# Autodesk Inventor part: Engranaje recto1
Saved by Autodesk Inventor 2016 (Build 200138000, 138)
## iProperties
Created: 2016-06
Part Number: Engranaje recto1
Material: Steel
Document SubType Name: Modeling
Designer: adm
Categories: <?xml version="1.0" encoding="UTF-16"?> <MemberInstance><Categories><FamilyTemplate><FamilyTemplateParameter ValueType="xs:double" Id="1" ObjectReferenceKey="da
Density: 1 g/cm^3
Appearance: Steel
CustomPartVersion: 1
Author: adm
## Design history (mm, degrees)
sketch "Sketch1"
  geometry: C1 r 25 at (0, 0)
  constraints: 1 centre point
  dimensions: "d0" = 50 diameter of C1 (= da_da)
extrude "Extrusion1" new body sketch "Sketch1" distance "d1" = 20 (= da_b); taper "d2" = 0 deg
workplane "Work Plane2"
sketch "Sketch2"
  geometry: C1 r 25 at (0, 0) reference; C2 r 23 at (0, 0)
  constraints: 1 centre point, 1 coincident
  dimensions: "d3" = 46 diameter of C2 (= da_dw)
feature "Diámetro de separación" sketch "Sketch2" dims "d4" = 10, "d5" = 0
workplane "Work Plane8"
workplane "Work Plane9"
feature "Engranaje recto" dims "d5" = 0, "da_b" = 20, "da_d" = 46, "da_aw" = 80, "da_da" = 50, "da_df" = 41, "da_dw" = 46, angle "da_beta" = 0 deg, "da_lefttooth" = 0, "da_righttooth" = 0
body "Solid1"
body "Srf1"
other parameters: "d17" = 0, "d34" = 1.36591 (computed from da_z), "d39" = 0, "d41" = 0, "d47" = 0, "d48" = 0
